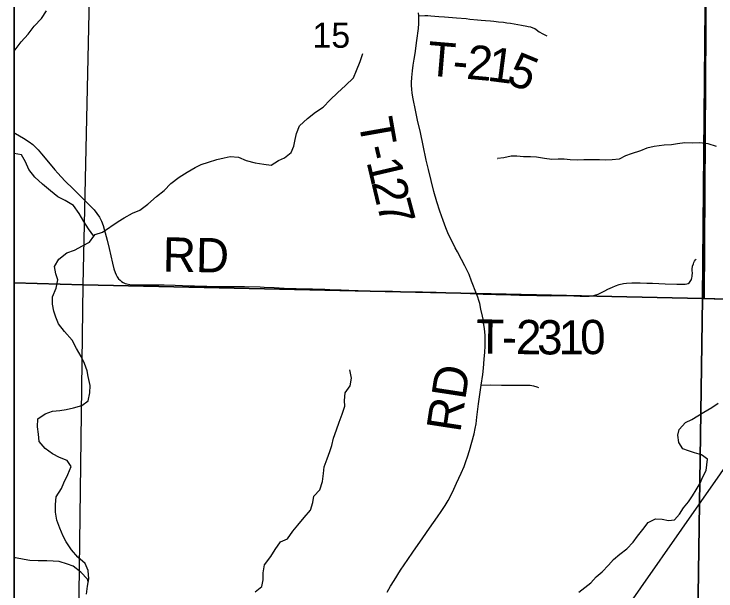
# Model space of a CAD drawing. Extents: x 0 to 34, y 0 to 22.
# Drawn here: x 1.631 to 2.794, y 18.731 to 19.687 of the extents above; entities that cross this region are included whole.
import ezdxf

# ---------------------------------------------------------------- set-up
doc = ezdxf.new("R2010")
doc.units = 0
for name, color, linetype in [('GM_X_Corporation', 7, 'Continuous'), ('GM_X_Minor_River', 7, 'Continuous'), ('GM_X_Rail_Line', 7, 'Continuous'), ('GM_X_Section_Text', 7, 'Continuous'), ('GM_X_Township_Road', 7, 'Continuous'), ('GM_X_Township_Road_Text', 7, 'Continuous'), ('SH_Text', 7, 'Continuous')]:
    doc.layers.add(name, color=color, linetype=linetype)

msp = doc.modelspace()

# ---------------------------------------------------------------- linework, layer by layer
at = {"layer": 'GM_X_Corporation'}
for points in [[(8.4311, 21.3734), (1.6311, 21.3734), (1.6311, 16.1731), (2.3716, 16.1532), (2.3935, 16.1523), (3.7652, 16.1115), (4.1576, 16.1007)], [(4.7823, 18.128), (4.0508, 18.1454), (3.7812, 18.1547), (3.7776, 18.3354), (3.7807, 18.4204), (3.7875, 18.9248), (3.7889, 19.1658), (3.7877, 19.187), (3.1142, 19.2057), (2.7749, 19.2162), (2.7798, 20.0198), (2.7831, 20.242), (2.7976, 21.3075), (2.7987, 21.3734), (1.6311, 21.3734), (1.6311, 16.1731), (2.3716, 16.1532), (2.3935, 16.1523), (3.7652, 16.1115), (4.1576, 16.1007)], [(8.4311, 21.3734), (2.7987, 21.3734), (2.7976, 21.3075), (2.7831, 20.242), (2.7798, 20.0198), (2.7749, 19.2162), (3.1142, 19.2057), (3.7877, 19.187), (3.7889, 19.1658), (3.7875, 18.9248), (3.7807, 18.4204), (3.7776, 18.3354), (3.7812, 18.1547), (4.0508, 18.1454), (4.7823, 18.128)]]:
    msp.add_lwpolyline(points, dxfattribs=at)
for points in [[(1.6311, 20.2706), (1.6311, 19.242), (1.7459, 19.2387), (1.7685, 20.2662)], [(2.7815, 20.2421), (2.7721, 19.2162), (1.7459, 19.2387), (1.7685, 20.2662)], [(3.8046, 20.2092), (3.7879, 19.187), (2.7721, 19.2162), (2.7815, 20.2421)], [(1.6311, 19.242), (1.6311, 18.2188), (1.7326, 18.216), (1.7459, 19.2387)], [(1.7459, 19.2387), (2.7721, 19.2162), (2.7572, 18.1961), (1.7326, 18.216)], [(3.7879, 19.187), (3.7781, 18.1522), (2.7572, 18.1961), (2.7721, 19.2162)]]:
    msp.add_lwpolyline(points, close=True, dxfattribs=at)
at = {"layer": 'GM_X_Minor_River'}
for points in [[(1.6311, 19.6257), (1.6329, 19.6281), (1.6431, 19.6411), (1.6543, 19.6541), (1.6645, 19.6674), (1.6769, 19.68), (1.6848, 19.693)], [(1.7635, 19.3193), (1.7654, 19.3219), (1.7779, 19.3262), (1.8039, 19.3438), (1.8137, 19.35), (1.8273, 19.3573), (1.8394, 19.3623), (1.8526, 19.3723), (1.867, 19.3849), (1.8798, 19.3948), (1.8907, 19.4067), (1.905, 19.417), (1.9179, 19.4255), (1.9311, 19.4331), (1.9413, 19.4381), (1.9534, 19.442), (1.967, 19.4463), (1.9795, 19.449), (1.9893, 19.4514), (2.003, 19.4503), (2.0159, 19.4447), (2.0307, 19.441), (2.0448, 19.4388), (2.0573, 19.437), (2.0694, 19.4447), (2.0792, 19.4493), (2.0905, 19.4581), (2.095, 19.4684), (2.0968, 19.4794), (2.099, 19.4893), (2.1039, 19.5022), (2.1174, 19.5145), (2.1306, 19.5248), (2.1431, 19.5333), (2.1547, 19.5455), (2.1672, 19.557), (2.1804, 19.5688), (2.1936, 19.5818), (2.1988, 19.594), (2.2044, 19.6088), (2.2092, 19.6218)], [(2.7952, 19.4679), (2.7815, 19.4723), (2.7668, 19.474), (2.7554, 19.4735), (2.7426, 19.4738), (2.7305, 19.4721), (2.7203, 19.4705), (2.7082, 19.47), (2.6916, 19.4679), (2.6795, 19.4651), (2.669, 19.4609), (2.6539, 19.4558), (2.6441, 19.4523), (2.6339, 19.4469), (2.6222, 19.446), (2.6116, 19.4455), (2.6011, 19.4458), (2.5882, 19.4456), (2.5753, 19.4459), (2.5648, 19.4454), (2.5527, 19.446), (2.5428, 19.447), (2.5326, 19.4469), (2.5224, 19.4464), (2.5103, 19.4482), (2.4967, 19.45), (2.4868, 19.451), (2.4755, 19.4509), (2.4645, 19.4519), (2.4547, 19.4518), (2.4426, 19.4494), (2.4324, 19.4478), (2.4328, 19.4478)], [(1.7513, 18.7263), (1.7531, 18.7392), (1.7549, 18.7518), (1.754, 18.7654), (1.749, 18.7771), (1.7368, 18.7877), (1.7265, 18.7994), (1.7177, 18.8126), (1.7127, 18.8224), (1.7069, 18.8357), (1.7023, 18.8489), (1.6999, 18.8618), (1.6998, 18.8747), (1.7012, 18.8877), (1.7095, 18.9014), (1.7136, 18.9109), (1.72, 18.9246), (1.7259, 18.9375), (1.7194, 18.9478), (1.7065, 18.9526), (1.6947, 18.9586), (1.6825, 18.9676), (1.673, 18.9789), (1.6714, 18.9911), (1.6698, 19.0036), (1.6704, 19.0165), (1.6829, 19.0249), (1.695, 19.0292), (1.7071, 19.0304), (1.7173, 19.0324), (1.7298, 19.0351), (1.7434, 19.0386), (1.754, 19.0467), (1.7566, 19.0596), (1.7572, 19.0721), (1.7537, 19.0869), (1.7525, 19.0964), (1.7479, 19.1085), (1.7425, 19.1202), (1.7345, 19.1335), (1.7272, 19.1471), (1.7149, 19.1614), (1.705, 19.1743), (1.7004, 19.1852), (1.6973, 19.1951), (1.6949, 19.2068), (1.6948, 19.219), (1.7012, 19.2331), (1.7037, 19.2471), (1.7003, 19.257), (1.6983, 19.2691), (1.7054, 19.2813), (1.7186, 19.2916), (1.7315, 19.2963), (1.7447, 19.3036), (1.7564, 19.3094), (1.7635, 19.3193), (1.7547, 19.3317), (1.7467, 19.3438), (1.739, 19.3571), (1.7294, 19.3703), (1.7161, 19.3785), (1.7039, 19.3845), (1.6917, 19.3943), (1.6784, 19.4056), (1.6654, 19.4169), (1.6555, 19.4298), (1.6501, 19.4426), (1.6436, 19.4543), (1.6314, 19.4562), (1.6311, 19.4559)], [(2.0306, 18.7301), (2.0416, 18.7389), (2.0442, 18.7499), (2.0441, 18.7617), (2.0463, 18.775), (2.0564, 18.7883), (2.0639, 18.8002), (2.0729, 18.8131), (2.0843, 18.8177), (2.0929, 18.8303), (2.1012, 18.8403), (2.1121, 18.8532), (2.1222, 18.8651), (2.1263, 18.878), (2.1281, 18.8883), (2.1379, 18.8993), (2.1424, 18.913), (2.1438, 18.9259), (2.1452, 18.937), (2.1501, 18.9503), (2.1542, 18.9628), (2.1575, 18.9723), (2.1605, 18.9849), (2.1653, 18.9982), (2.1698, 19.0111), (2.175, 19.0245), (2.1794, 19.0374), (2.1786, 19.0473), (2.18, 19.0598), (2.1879, 19.0716), (2.1901, 19.0842), (2.1874, 19.0978)], [(2.5672, 18.7294), (2.5867, 18.7447), (2.5957, 18.7547), (2.6055, 18.7631), (2.616, 18.7742), (2.6242, 18.7838), (2.6351, 18.7922), (2.6464, 18.8014), (2.6572, 18.8125), (2.6643, 18.8224), (2.6729, 18.8335), (2.6819, 18.845), (2.6943, 18.8512), (2.7049, 18.8505), (2.7155, 18.848), (2.7257, 18.8492), (2.7339, 18.8588), (2.7406, 18.8691), (2.7489, 18.879), (2.7552, 18.8889), (2.7612, 18.8992), (2.7679, 18.9099), (2.7727, 18.9206), (2.7779, 18.9308), (2.78, 18.9498), (2.7701, 18.9569), (2.7584, 18.9606), (2.7489, 18.9635), (2.7394, 18.9672), (2.7325, 18.9777), (2.7313, 18.9895), (2.7331, 18.999), (2.7436, 19.0104), (2.7541, 19.0155), (2.7643, 19.0216), (2.774, 19.0278), (2.7876, 19.0355), (2.7977, 19.0428)], [(1.7542, 18.747), (1.753, 18.751), (1.7419, 18.7627), (1.729, 18.7725), (1.7195, 18.7758), (1.7058, 18.7803), (1.6959, 18.7806), (1.6853, 18.7813), (1.6709, 18.7816), (1.6572, 18.7818), (1.6477, 18.7837), (1.6337, 18.7862), (1.6311, 18.7861)]]:
    msp.add_lwpolyline(points, dxfattribs=at)
at = {"layer": 'GM_X_Rail_Line'}
msp.add_lwpolyline([(4.1788, 20.304), (4.0429, 20.1945), (3.3384, 19.6119), (3.2847, 19.5633), (3.2446, 19.5253), (3.2015, 19.4768), (3.1607, 19.4315), (3.1275, 19.3905), (3.0936, 19.3436), (2.5732, 18.599), (2.0707, 17.885), (2.0334, 17.8382), (1.9924, 17.7972), (1.9547, 17.7644), (1.7027, 17.5707), (1.6311, 17.5139)], dxfattribs=at)
at = {"layer": 'GM_X_Township_Road'}
for points in [[(2.3977, 19.2236), (2.3894, 19.2447), (2.385, 19.2556), (2.3815, 19.2636), (2.3783, 19.2703), (2.3728, 19.2807), (2.3658, 19.2932), (2.362, 19.3003), (2.3563, 19.3114), (2.3513, 19.322), (2.3467, 19.3329), (2.342, 19.3451), (2.3365, 19.3609), (2.3317, 19.3764), (2.3269, 19.3931), (2.3221, 19.4117), (2.3177, 19.4298), (2.3142, 19.4455), (2.3092, 19.4698), (2.3044, 19.491), (2.2997, 19.5116), (2.2962, 19.528), (2.2924, 19.5469), (2.2908, 19.5561), (2.29, 19.5629), (2.2896, 19.5691), (2.2896, 19.5741), (2.2901, 19.5821), (2.2913, 19.5932), (2.2927, 19.6029), (2.2943, 19.6126), (2.2958, 19.6223), (2.2988, 19.6438), (2.3012, 19.6635), (2.3018, 19.6716), (2.3018, 19.6765), (2.302, 19.6845)], [(2.302, 19.6845), (2.3011, 19.6893)], [(2.302, 19.6845), (2.312, 19.6849), (2.3166, 19.6848), (2.3216, 19.6844), (2.3352, 19.6833), (2.3444, 19.6827), (2.3643, 19.6811), (2.3804, 19.6798), (2.3865, 19.6792), (2.3989, 19.6781), (2.4051, 19.6775), (2.4125, 19.6767), (2.4205, 19.6759), (2.4261, 19.6754), (2.4341, 19.6746), (2.4421, 19.6737), (2.4477, 19.673), (2.4539, 19.6723), (2.46, 19.6713), (2.4661, 19.6703), (2.4722, 19.6691), (2.4807, 19.6675), (2.4832, 19.6669), (2.4868, 19.6661), (2.4909, 19.6648), (2.4943, 19.6632), (2.4963, 19.6618), (2.5013, 19.6581), (2.5071, 19.6546), (2.5126, 19.6517), (2.5137, 19.6512)], [(1.6311, 19.4907), (1.6334, 19.4894), (1.6469, 19.4816), (1.6562, 19.4756), (1.6621, 19.471), (1.6671, 19.4664), (1.6711, 19.4624), (1.6769, 19.4559), (1.6938, 19.4352), (1.699, 19.4291), (1.7036, 19.424), (1.7155, 19.4113), (1.7294, 19.3971), (1.752, 19.3749), (1.7586, 19.3683), (1.7637, 19.3629), (1.7684, 19.3571), (1.7725, 19.3509), (1.7759, 19.3443), (1.7786, 19.3373), (1.7824, 19.3248), (1.7857, 19.3129), (1.789, 19.299), (1.7941, 19.2746), (1.7965, 19.265), (1.7985, 19.2591), (1.8002, 19.2551), (1.8021, 19.2519), (1.8043, 19.2489), (1.8069, 19.2463), (1.8093, 19.2443), (1.8119, 19.2427), (1.8153, 19.2412), (1.8183, 19.2404), (1.8232, 19.2394), (1.8281, 19.2389), (1.8343, 19.2388), (1.8511, 19.2389), (1.8604, 19.2389), (1.8797, 19.2387), (1.8983, 19.2382), (1.91, 19.2378), (1.9223, 19.2373), (1.9303, 19.237), (1.9364, 19.2367), (1.9474, 19.2365), (1.9505, 19.2364), (1.9678, 19.2362), (1.9764, 19.2362), (1.9912, 19.2362), (1.9999, 19.2361), (2.0049, 19.2359), (2.0129, 19.2357), (2.039, 19.2353), (2.0458, 19.235), (2.062, 19.2341), (2.0787, 19.2333), (2.0986, 19.2326), (2.1122, 19.2321), (2.1178, 19.232), (2.1258, 19.2319), (2.1358, 19.2315), (2.1463, 19.2313), (2.163, 19.2306), (2.173, 19.2303), (2.186, 19.2299), (2.2015, 19.2293), (2.2152, 19.2288), (2.2337, 19.2284), (2.2461, 19.2284), (2.251, 19.2283), (2.2585, 19.2281), (2.2634, 19.2279), (2.2703, 19.2277), (2.2919, 19.2272), (2.3081, 19.227), (2.3304, 19.2267), (2.3762, 19.2248), (2.3977, 19.2236)], [(2.3977, 19.2236), (2.4085, 19.2235), (2.4184, 19.2232), (2.4296, 19.2229), (2.4401, 19.2226), (2.4687, 19.2218), (2.4972, 19.221), (2.509, 19.2208), (2.5195, 19.2207), (2.5269, 19.2208), (2.5479, 19.2209), (2.5693, 19.2201), (2.5785, 19.2199), (2.584, 19.22), (2.5883, 19.2204), (2.5912, 19.221), (2.5937, 19.2216), (2.5989, 19.2235), (2.6045, 19.2262), (2.61, 19.229), (2.615, 19.2316), (2.6229, 19.2351), (2.6275, 19.2369), (2.6339, 19.2391), (2.6412, 19.2407), (2.6461, 19.2415), (2.6547, 19.2423), (2.6628, 19.2423), (2.6684, 19.2421), (2.6795, 19.2417), (2.6888, 19.2413), (2.7099, 19.2404), (2.7292, 19.2399), (2.7373, 19.2396), (2.7404, 19.2396), (2.7434, 19.2398), (2.746, 19.2402), (2.7481, 19.2411), (2.7501, 19.2425), (2.7515, 19.2441), (2.7528, 19.246), (2.7536, 19.2478), (2.7543, 19.2502), (2.7548, 19.2525), (2.7549, 19.2544), (2.7551, 19.2582), (2.7549, 19.2625), (2.7549, 19.2656), (2.755, 19.2669), (2.7552, 19.268), (2.7556, 19.2698), (2.7568, 19.2733), (2.7578, 19.2755), (2.7588, 19.2778), (2.7601, 19.2799), (2.7613, 19.2812)], [(2.4053, 19.0726), (2.4077, 19.0902), (2.4089, 19.1007), (2.4104, 19.1155), (2.4112, 19.1272), (2.4119, 19.1371), (2.412, 19.1501), (2.4118, 19.1553), (2.4115, 19.1601), (2.4108, 19.1662), (2.4093, 19.176), (2.4082, 19.1821), (2.4073, 19.187), (2.4047, 19.1986), (2.4027, 19.2076), (2.4012, 19.213), (2.3995, 19.2183), (2.3977, 19.2236)], [(2.2496, 18.7297), (2.2552, 18.7394), (2.261, 18.7489), (2.2717, 18.7657), (2.2839, 18.7837), (2.2922, 18.796), (2.3084, 18.8195), (2.3194, 18.8353), (2.3326, 18.8541), (2.3389, 18.8633), (2.3454, 18.8731), (2.3506, 18.8816), (2.3544, 18.8887), (2.3601, 18.9004), (2.3645, 18.91), (2.372, 18.9264), (2.3769, 18.9378), (2.38, 18.9459), (2.3827, 18.9535), (2.3861, 18.9642), (2.3899, 18.9779), (2.3934, 18.9918), (2.3953, 19.0009), (2.3966, 19.0082), (2.3981, 19.0193), (2.4009, 19.0415), (2.4053, 19.0726)], [(2.4053, 19.0726), (2.4208, 19.0729), (2.4388, 19.0724), (2.4518, 19.0724), (2.4636, 19.0725), (2.4772, 19.0725), (2.4865, 19.0723), (2.489, 19.072), (2.492, 19.0714), (2.4972, 19.0695), (2.5001, 19.0685)]]:
    msp.add_lwpolyline(points, dxfattribs=at)
at = {"layer": 'SH_Text'}
msp.add_line((1.6311, 14.5734), (1.6311, 21.3734), dxfattribs=at)

# ---------------------------------------------------------------- texts
at = {"layer": 'GM_X_Section_Text'}
msp.add_text('15', height=0.04186, rotation=0, dxfattribs=at).set_placement((2.1258, 19.6315))
at = {"layer": 'GM_X_Township_Road_Text'}
for s, height, rotation, p in [('T', 0.0568, 355.2549, (2.3141, 19.5858)), ('2', 0.0568, 354.8072, (2.3795, 19.5803)), ('1', 0.0568, 352.6471, (2.4138, 19.5772)), ('5', 0.0568, 337.6536, (2.4448, 19.5738)), ('-', 0.0568, 355.1819, (2.3564, 19.5823)), ('T', 0.0568, 279.9714, (2.2015, 19.5108)), ('-', 0.0568, 283.2033, (2.2096, 19.4655)), ('1', 0.0568, 283.1887, (2.2149, 19.4428)), ('2', 0.0568, 283.4081, (2.223, 19.4085)), ('7', 0.0568, 284.9397, (2.2315, 19.3729)), ('RD', 0.05682, 359.024, (1.8772, 19.2608)), ('T', 0.0568, 359.2993, (2.3967, 19.1248)), ('2', 0.0568, 359.3203, (2.4625, 19.124)), ('3', 0.0568, 359.474, (2.4977, 19.1236)), ('1', 0.0568, 359.9802, (2.5332, 19.1233)), ('0', 0.0568, 1.5368, (2.5699, 19.1233)), ('-', 0.0568, 359.2974, (2.4392, 19.1243)), ('RD', 0.05682, 81.3193, (2.3704, 18.9928))]:
    msp.add_text(s, height=height, rotation=rotation, dxfattribs=at).set_placement(p)

doc.saveas('drawing.dxf')
